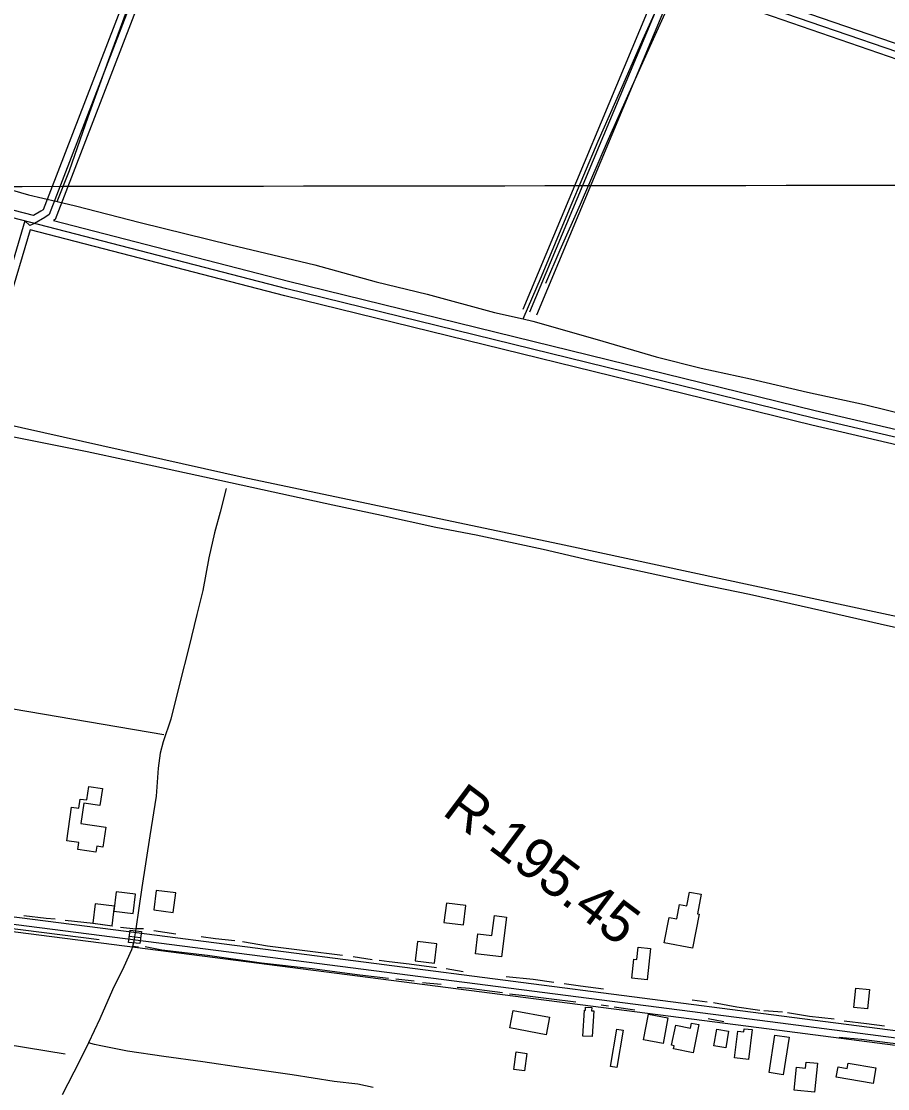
# Model space of a CAD drawing. Extents: x 3324104 to 3361979, y 612876 to 638273.
# Drawn here: x 3330840 to 3332612, y 622475 to 624660 of the extents above; entities that cross this region are included whole.
import ezdxf

# ---------------------------------------------------------------- set-up
doc = ezdxf.new("R2010")
doc.units = 0
for name, color, linetype in [('V-BLDG-OTLN', 7, 'Continuous'), ('V-BRDG-OTLN', 7, 'Continuous'), ('V-DTCH-CNTR', 7, 'Continuous'), ('V-GRID-MAJR', 7, 'Continuous'), ('V-RIVR-RANG-IDEN', 7, 'Continuous'), ('V-ROAD-CNTR', 7, 'Continuous'), ('V-TOPO-SHOR', 7, 'Continuous')]:
    doc.layers.add(name, color=color, linetype=linetype)

msp = doc.modelspace()

# ---------------------------------------------------------------- linework, layer by layer
at = {"layer": 'V-BLDG-OTLN'}
for points in [[(3330933.5, 622982.3), (3330943.1, 623051.3), (3330958.1, 623049.3), (3330960.7, 623067.9), (3330974.4, 623066), (3330978.2, 623093.5), (3331005.9, 623089.7), (3331001.1, 623054.9), (3330967.7, 623059.6), (3330961.9, 623017.7), (3331012.8, 623010.6), (3331007.1, 622969.6), (3330994.3, 622971.4), (3330992.6, 622959.1), (3330955.6, 622964.3), (3330957.6, 622979)], [(3331111.3, 622840.9), (3331151, 622835.9), (3331156, 622875.6), (3331116.3, 622880.6)], [(3331029.2, 622838.6), (3331068.8, 622833.6), (3331073.8, 622873.3), (3331034.1, 622878.3)], [(3332213.5, 622762.4), (3332155.5, 622773.5), (3332165.5, 622825.6), (3332181.2, 622822.6), (3332186.9, 622851.8), (3332201.7, 622849), (3332207.2, 622877.5), (3332230.9, 622872.9), (3332223.2, 622832.8), (3332227, 622832.1)], [(3330986.3, 622813.7), (3331026, 622808.7), (3331031, 622848.4), (3330991.3, 622853.4)], [(3331704.8, 622815.3), (3331744.5, 622810.3), (3331749.5, 622850), (3331709.8, 622855)], [(3331832.7, 622826.2), (3331822.2, 622744.6), (3331769, 622751.4), (3331774.2, 622792.3), (3331803, 622788.6), (3331808.3, 622829.4)], [(3331645.6, 622736.7), (3331685.3, 622731.7), (3331690.2, 622771.4), (3331650.6, 622776.3)], [(3332127.3, 622761.7), (3332120.3, 622697.7), (3332088.8, 622701.1), (3332093, 622739.9), (3332099.4, 622739.2), (3332102.2, 622764.5)], [(3332543.6, 622640.9), (3332547.5, 622680.8), (3332575.2, 622678.1), (3332571.3, 622638.2)], [(3332011.2, 622634.2), (3332007.9, 622581.7), (3331989.2, 622582.9), (3331992.5, 622635.9), (3331994, 622635.8), (3331994.4, 622642), (3332007.2, 622641.2), (3332006.7, 622634.4)], [(3331846.1, 622635.3), (3331920.9, 622621.5), (3331914.2, 622585.6), (3331839.5, 622599.5)], [(3332162.9, 622619.9), (3332153.1, 622567.5), (3332113.3, 622574.9), (3332123.1, 622627.4)], [(3332071.3, 622594.7), (3332058.4, 622518.6), (3332045.3, 622520.8), (3332058.2, 622596.9)], [(3332226, 622606.5), (3332214.4, 622548.4), (3332174.6, 622556.4), (3332175.9, 622562.9), (3332170.6, 622564), (3332178.9, 622605.3), (3332209.4, 622599.2), (3332211.4, 622609.4)], [(3332262.7, 622597), (3332286.9, 622593), (3332281.2, 622559), (3332257.1, 622563)], [(3332299.3, 622537.9), (3332305.9, 622593.1), (3332318.5, 622591.6), (3332319.2, 622597.9), (3332335.1, 622596.1), (3332327.8, 622534.6)], [(3332410.8, 622580.5), (3332398.8, 622503.4), (3332370, 622507.9), (3332382, 622584.9)], [(3331874.1, 622547.4), (3331869.3, 622511.7), (3331847.6, 622514.6), (3331852.4, 622550.3)], [(3332469.1, 622527.1), (3332463, 622467.7), (3332421.3, 622472), (3332426.1, 622519.1), (3332444.3, 622517.2), (3332445.6, 622529.5)], [(3332531.7, 622527.5), (3332588.3, 622517.7), (3332582.7, 622485.5), (3332507.3, 622498.6), (3332511, 622519.6), (3332529.8, 622516.4)]]:
    msp.add_lwpolyline(points, close=True, dxfattribs=at)
at = {"layer": 'V-BRDG-OTLN'}
msp.add_lwpolyline([(3331082.5, 622772.1), (3331059.2, 622774.5), (3331063.1, 622799.7), (3331086.1, 622796.8)], close=True, dxfattribs=at)
msp.add_lwpolyline([(3331061.2, 622787.5), (3331071.8, 622786), (3331084.3, 622784.3), (3331084.3, 622784.3)], dxfattribs=at)
at = {"layer": 'V-DTCH-CNTR'}
for points in [[(3330913.6, 624290.6), (3330938.6, 624354.6), (3330977.2, 624463.8), (3331018.3, 624579.4), (3331055.3, 624679.5), (3331095.5, 624790.9), (3331132, 624887.8), (3331175.8, 625005.1), (3331211.2, 625091.2), (3331247.2, 625178.6), (3331289, 625288.9), (3331330.2, 625392.3), (3331358.3, 625458.8)], [(3331866.7, 624050.7), (3331904.3, 624137), (3331961.8, 624275.1), (3332020.3, 624414.2), (3332066.9, 624519.2), (3332111.8, 624622.6), (3332156.3, 624722.3)], [(3330723.1, 624342.9), (3330854.6, 624304.5), (3330913.6, 624290.6), (3330951, 624281.8), (3331083, 624247.7), (3331268.8, 624202.2), (3331440.7, 624161.5), (3331565.8, 624126.3), (3331670.2, 624101), (3331808.1, 624063.7), (3331866.7, 624050.7), (3331886.8, 624046.2), (3332018.4, 624008.3), (3332138.7, 623973.1), (3332230.8, 623949.8), (3332331.9, 623928.2), (3332448.5, 623900.9), (3332565, 623875.1), (3332656.6, 623853)], [(3332729.8, 623396.2), (3332606.3, 623423.5), (3332477.5, 623453.4), (3332330.1, 623486.3), (3332226.9, 623507.9), (3332110.9, 623532.6), (3332003.9, 623556.2), (3331907.5, 623578.4), (3331770.8, 623608.2), (3331688.3, 623623.6), (3331577.1, 623648.3), (3331477.5, 623669.4), (3331355.1, 623696.1), (3331246, 623719.8), (3331111.4, 623749.1), (3331057.4, 623761), (3330974.6, 623778.4), (3330892.7, 623794.9), (3330804.1, 623812.8)]]:
    msp.add_lwpolyline(points, dxfattribs=at)
at = {"layer": 'V-GRID-MAJR'}
msp.add_spline([(3328210, 624318.2), (3333474, 624325.5), (3338738.1, 624333.5), (3344002.2, 624342.3), (3349266.2, 624351.9), (3354530.3, 624362.2), (3359794.3, 624373.3)], degree=3, dxfattribs=at)
at = {"layer": 'V-ROAD-CNTR'}
for points in [[(3328228.4, 626090.9), (3329021.9, 625817), (3329615.9, 625618.6), (3329853.6, 625522.1), (3329993.2, 625472.5), (3330171.3, 625413.7), (3330344.3, 625366.1), (3330475.1, 625322.3), (3330691, 625264), (3330952.9, 625174.1), (3331410, 625011.9), (3331598.3, 624955), (3331776.8, 624896.8), (3331967.1, 624825.6), (3332127.8, 624779.8), (3332302, 624711.1), (3332836.1, 624527.5)], [(3331355.2, 625452.5), (3330897.2, 624264.1), (3330888.2, 624258.3), (3330867.3, 624246), (3330857.6, 624241.4), (3330847.6, 624251.1)], [(3331192.9, 625073), (3330885, 624274.1), (3330880.4, 624271.1), (3330865, 624262.1)], [(3331221.2, 625063), (3330909.5, 624254), (3330905.8, 624251.7)], [(3332173.6, 624766.7), (3331880.1, 624064.1)], [(3332152.1, 624754.1), (3331866.3, 624069.9)], [(3332180, 624743.1), (3331894, 624058.3)], [(3332238.3, 624752.4), (3332307.1, 624725.2), (3332840.9, 624541.7), (3333384.4, 624360.1), (3333502.9, 624324.9)], [(3332234, 624721.8), (3332296.8, 624697.1), (3332831.3, 624513.3), (3333375.4, 624331.5), (3333491.3, 624297.1)], [(3333865.1, 623274.4), (3333788, 623355.3), (3333754.5, 623362.2), (3333671.3, 623390.9), (3333167.1, 623510.6), (3333160.6, 623516.6), (3333157.7, 623522), (3333191.8, 623647.2), (3333191.4, 623657.4), (3333183, 623673.5), (3333174.8, 623681.1), (3332460.7, 623847.7), (3331383.1, 624112.4), (3329821.9, 624516.6), (3329265.2, 624654.6), (3329210.1, 624671.3), (3329158, 624668.4), (3329138.2, 624661.2), (3329123.5, 624653.6), (3329118.4, 624643.8), (3329110.3, 624628.2), (3328995.8, 624237.3)], [(3330865, 624262.1), (3329825.6, 624531.2), (3329269.2, 624669), (3329229.5, 624681.1)], [(3330857.9, 624232.9), (3330812.4, 624078.7), (3330793.8, 623981.1), (3330770.3, 623850.3)], [(3330847.6, 624251.1), (3330797.8, 624082.2)], [(3333854.3, 623264.1), (3333780.4, 623341.5), (3333750.5, 623347.7), (3333667.1, 623376.5), (3333159.9, 623496.9), (3333148.5, 623507.3), (3333141.7, 623520.3), (3333176.7, 623648.8), (3333176.5, 623653.5), (3333170.9, 623664.3), (3333167.5, 623667.4), (3332457.2, 623833.1), (3331379.4, 624097.9), (3330857.9, 624232.9)], [(3333876, 623284.8), (3333795.6, 623369), (3333758.5, 623376.7), (3333675.5, 623405.4), (3333174.3, 623524.3), (3333172.7, 623525.9), (3333173.8, 623523.8), (3333206.9, 623645.5), (3333206.2, 623661.4), (3333195.1, 623682.8), (3333182, 623694.8), (3332464.2, 623862.2), (3331386.8, 624127), (3330906, 624251.4)], [(3333257.9, 622512), (3332374.2, 622626.5), (3331054.8, 622796.6), (3329611.8, 622981.7)], [(3333256, 622497.1), (3332372.2, 622611.6), (3331052.9, 622781.7), (3329613.2, 622966.4)], [(3333254.1, 622482.2), (3332370.3, 622596.7), (3331051, 622766.8), (3329643.6, 622947.4)]]:
    msp.add_lwpolyline(points, dxfattribs=at)
at = {"layer": 'V-TOPO-SHOR'}
for p, q in [((3329808.4, 623424.2), (3331131.8, 623199.9)), ((3331043.2, 622805.7), (3331074.7, 622802.1)), ((3331090.2, 622802), (3331074.7, 622802.1)), ((3331155.9, 622791.2), (3331111.5, 622798)), ((3331080.1, 622764.6), (3331067.4, 622766.4)), ((3331557.8, 622738.9), (3331519, 622744.6)), ((3331744.4, 622714.2), (3331709, 622720.6)), ((3331643.9, 622695.2), (3331606.6, 622699)), ((3331699.1, 622688.1), (3331661.1, 622691.9)), ((3332041.7, 622644.3), (3332026.4, 622646.1)), ((3332095.5, 622635.8), (3332053.3, 622642.2)), ((3332243.4, 622652.1), (3332212.4, 622656)), ((3332277.6, 622612.1), (3332245.5, 622617.8)), ((3332397.5, 622632), (3332359.5, 622634.7))]:
    msp.add_line(p, q, dxfattribs=at)
for points in [[(3331913.4, 624123.4), (3331942.2, 624191.6), (3331984, 624285.4), (3332041.5, 624418.7), (3332080.7, 624507.2), (3332126.8, 624608.4), (3332177.5, 624722), (3332188.6, 624751.7)], [(3328210.3, 624414.6), (3328900.4, 624252.5), (3329573.9, 624100.4), (3330414, 623915.2), (3330760.8, 623845.8), (3331294.2, 623726.8), (3331951, 623588), (3332857.8, 623392.9), (3333284.6, 623290.3), (3333468, 623250.7), (3333768, 623207.9), (3333671.5, 623087.7)], [(3331259, 623703.6), (3331246.9, 623655), (3331235.6, 623612.7), (3331223.9, 623561.6), (3331211.2, 623494.8), (3331199.5, 623445.8), (3331183, 623378.2), (3331164.5, 623305.5), (3331145.9, 623231.6), (3331130.5, 623184.7), (3331124.5, 623161.5), (3331120.1, 623131.2), (3331116, 623074), (3331103.3, 622992.7), (3331086.6, 622886.9), (3331074.7, 622802.1), (3331071.8, 622786)], [(3330999.3, 622779.8), (3330532.6, 622838.9), (3329719.2, 622940.8)], [(3330845.4, 622829.7), (3330890.8, 622824), (3330909.6, 622822.7)], [(3330930.1, 622820.2), (3330987.1, 622813.5), (3331026.8, 622808.2)], [(3331071.8, 622786), (3331070, 622776.5), (3331067.4, 622766.4), (3331065.6, 622759.5), (3331049.7, 622724.2), (3331026.4, 622677.2), (3331000.7, 622618.2), (3330977.4, 622569), (3330959.5, 622531.3), (3330923.9, 622462.6)], [(3331277.2, 622777.6), (3331237.1, 622782), (3331208.2, 622785.6)], [(3331497.4, 622747.8), (3331420.1, 622757.2), (3331343.9, 622767.1), (3331292.5, 622775.4)], [(3329579.6, 622760.6), (3330646.3, 622592.5), (3330929.7, 622546.4)], [(3331591.3, 622700.8), (3331532.6, 622707.3), (3331435.1, 622720.4), (3331331.7, 622732.3), (3331221.2, 622748), (3331127.9, 622758.9), (3331093.5, 622765.4)], [(3331689.2, 622722.7), (3331633.9, 622729.6), (3331592.5, 622734.5), (3331572, 622737.5)], [(3331929.5, 622692.4), (3331887, 622698.2), (3331831.8, 622704.3)], [(3331824.5, 622671.5), (3331787.9, 622675.9), (3331756.9, 622680.2), (3331732, 622682.4)], [(3332031, 622678.9), (3331984.4, 622684.7), (3331950.4, 622689.5)], [(3331974.6, 622652.4), (3331919.3, 622659), (3331870, 622665), (3331838.7, 622668.6)], [(3332350.9, 622635.4), (3332303.6, 622641.9), (3332256.1, 622651.1)], [(3332503.1, 622617.1), (3332452.6, 622622.8), (3332407.6, 622630.2)], [(3332605.8, 622602.9), (3332569, 622608), (3332523.3, 622613.5)], [(3332675, 622562), (3332617.3, 622568.5), (3332558.7, 622575.5), (3332513.5, 622579.5)], [(3331560, 622477.3), (3331528.4, 622484), (3331479.9, 622490), (3331394, 622503.5), (3331294.3, 622517.7), (3331211.4, 622529.8), (3331131.9, 622541.2), (3331057.6, 622552.2), (3331002.7, 622562.6), (3330990, 622565.5), (3330977.4, 622569)]]:
    msp.add_lwpolyline(points, dxfattribs=at)

# ---------------------------------------------------------------- texts
at = {"layer": 'V-RIVR-RANG-IDEN'}
msp.add_text('R-195.45', height=83, rotation=323.2383, dxfattribs=at).set_placement((3331698.8, 623037.9))

doc.saveas('drawing.dxf')
